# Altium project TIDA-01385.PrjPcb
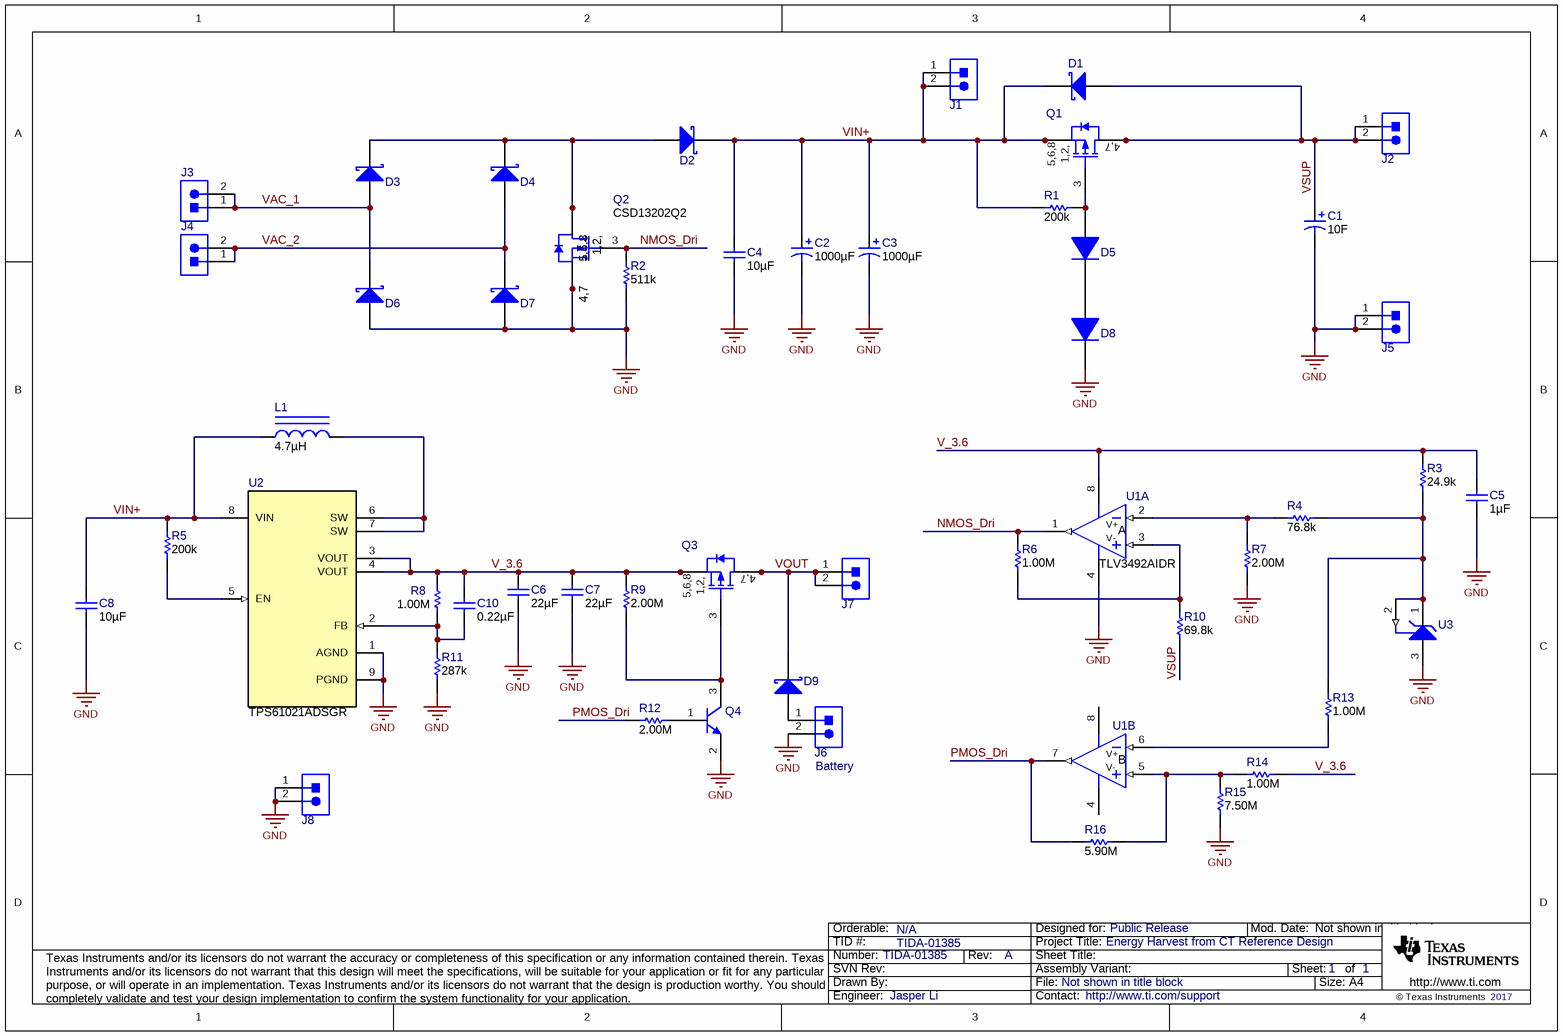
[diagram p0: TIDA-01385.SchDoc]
TID: TIDA-01385; TechSupport: http://www.ti.com/support; SCH_Rev: A; PRJ_Title: Energy Harvest from CT Reference Design; PRJ_Number: TIDA-01385; PRJ_Engineer: Jasper Li; PRJ_Customer: Public Release; PCB_Rev: A; PCB_Layout: Jasper Li; EVM_orderable: N/A; CopyrightYear: 2017
1 sheet, 50 parts. Net scope: global (net labels, ports and power ports of the same name join across sheets).
Board file: TIDA-01385_PCB.PcbDoc

## Sheet TIDA-01385.SchDoc
size A4; Date: Not shown in title block; ApprovedBy: Not shown in title block; CheckedBy: Not shown in title block; Author: Not shown in title block; CompanyName: Not shown in title block; Engineer: Not shown in title block; Organization: Not shown in title block; Address1: Not shown in title block; Address2: Not shown in title block; Address3: Not shown in title block; Address4: Not shown in title block; DocumentNumber: 1; Revision: Use project parameter SCH_Rev; SheetNumber: 1; SheetTotal: 1; PageSetup: Record=PageOptions¦CenterHorizontal=True¦CenterVertical=True¦PrintScale=0.91¦XCorrection=1.00¦YCorrection=1.00¦PrintKind=0¦BorderSize=5000000¦LeftOffset=0¦BottomOffset=0¦Orientation=2¦PaperLength=1000¦PaperWidth=1000¦Scale=100¦PaperSource=15¦PrintQuality=600¦MediaType=1¦DitherType=10¦PrintScaleMode=1¦PaperKind=Letter

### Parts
C1  ValueDisplayed: 10F  [ZL_1000x2300]  (hidden comment: 100ZL100MEFC10X23)
C2  ValueDisplayed: 1000µF  [EB_1000x2000]  (hidden comment: EEU-EB1C102)
C3  ValueDisplayed: 1000µF  [EB_1000x2000]  (hidden comment: EEU-EB1C102)
C4  ValueDisplayed: 10µF  [0603]  (hidden comment: GRM188R60J106ME47D)
C5  ValueDisplayed: 1µF  [0603]  (hidden comment: GRM185R60J105KE26D)
C6  ValueDisplayed: 22µF  [0603]  (hidden comment: GRM188R60J226MEA0D)
C7  ValueDisplayed: 22µF  [0603]  (hidden comment: GRM188R60J226MEA0D)
C8  ValueDisplayed: 10µF  [0603]  (hidden comment: GRM188R60J106ME47D)
C10  ValueDisplayed: 0.22µF  [0603]  (hidden comment: GRM188R61A224KA01D)
D1  SL22-E3/52T  [SMB]  (value not drawn)
D2  SL22-E3/52T  [SMB]  (value not drawn)
D3  SL22-E3/52T  [SMB]  (value not drawn)
D4  SL22-E3/52T  [SMB]  (value not drawn)
D5  1N4148W-7-F  [SOD-123]  (value not drawn)
D6  SL22-E3/52T  [SMB]  (value not drawn)
D7  SL22-E3/52T  [SMB]  (value not drawn)
D8  1N4148W-7-F  [SOD-123]  (value not drawn)
D9  BAT54WS-7-F  [SOD-323]  (value not drawn)
J1  TSW-102-07-G-S  [TSW-102-07-G-S]  (value not drawn)
J2  TSW-102-07-G-S  [TSW-102-07-G-S]  (value not drawn)
J3  TSW-102-07-G-S  [TSW-102-07-G-S]  (value not drawn)
J4  TSW-102-07-G-S  [TSW-102-07-G-S]  (value not drawn)
J5  TSW-102-07-G-S  [TSW-102-07-G-S]  (value not drawn)
J6  TSW-102-07-G-S  [TSW-102-07-G-S]  (value not drawn)
J7  TSW-102-07-G-S  [TSW-102-07-G-S]  (value not drawn)
J8  TSW-102-07-G-S  [TSW-102-07-G-S]  (value not drawn)
L1  ValueDisplayed: 4.7µH  [WE-PMI_1008]  (hidden comment: 74479887247)
Q1  CSD25310Q2  [DQK0006C]  (value not drawn)
Q2  CSD13202Q2  [DQK0006C]
Q3  CSD25310Q2  [DQK0006C]  (value not drawn)
Q4  MMBT3904  [SOT-23]  (value not drawn)
R1  ValueDisplayed: 200k  [0603]  (hidden comment: CRCW0603200KFKEA)
R2  ValueDisplayed: 511k  [0603]  (hidden comment: RC0603FR-07511KL)
R3  ValueDisplayed: 24.9k  [0603]  (hidden comment: CRCW060324K9FKEA)
R4  ValueDisplayed: 76.8k  [0603]  (hidden comment: CRCW060376K8FKEA)
R5  ValueDisplayed: 200k  [0603]  (hidden comment: CRCW0603200KFKEA)
R6  ValueDisplayed: 1.00M  [0603]  (hidden comment: CRCW06031M00FKEA)
R7  ValueDisplayed: 2.00M  [0603]  (hidden comment: CRCW06032M00FKEA)
R8  ValueDisplayed: 1.00M  [0603]  (hidden comment: CRCW06031M00FKEA)
R9  ValueDisplayed: 2.00M  [0603]  (hidden comment: CRCW06032M00FKEA)
R10  ValueDisplayed: 69.8k  [0603]  (hidden comment: RC0603FR-0769K8L)
R11  ValueDisplayed: 287k  [0603]  (hidden comment: CRCW0603287KFKEA)
R12  ValueDisplayed: 2.00M  [0603]  (hidden comment: CRCW06032M00FKEA)
R13  ValueDisplayed: 1.00M  [0603]  (hidden comment: CRCW06031M00FKEA)
R14  ValueDisplayed: 1.00M  [0603]  (hidden comment: CRCW06031M00FKEA)
R15  ValueDisplayed: 7.50M  [0603]  (hidden comment: CRCW06037M50FKEA)
R16  ValueDisplayed: 5.90M  [0603]  (hidden comment: CRCW06035M90FKEA)
U1  TLV3492AIDR  [D0008A_N]  (parts A,B of 2)
U2  TPS61021ADSGR  [DSG0008A]
U3  ATL431AIDBZR  [DBZ0003A_N]  (value not drawn)

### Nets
GND: C1.2(-) C2.2(-) C3.2(-) C4.2 C5.2 C6.2 C7.2 C8.2 D6.2(A) D7.2(A) D8.1(K) J5.1 J5.2 J6.2 J8.1 J8.2 Q2.4(S) Q2.7(S) Q4.2(E) R2.1 R7.1 R11.1 R15.1 U1.4(V-) U2.1(AGND) U2.9(PGND) U3.3(ANODE)
NMOS_Dri: Q2.3(G) R2.2 R6.2 U1.1(OUT)
PMOS_Dri: R12.2 R16.2 U1.7(OUT)
V_3.6: C5.1 C6.1 C7.1 C10.1 Q3.1(S) Q3.2(S) Q3.5(S) Q3.6(S) Q3.8(S) R3.2 R8.2 R9.2 R14.1 U1.8(V+) U2.3(VOUT) U2.4(VOUT)
VAC_1: D3.2(A) D6.1(K) J3.1 J3.2
VAC_2: D4.2(A) D7.1(K) J4.1 J4.2
VIN+: C2.1(+) C3.1(+) C4.1 C8.1 D1.1(K) D2.1(K) J1.1 J1.2 L1.1 Q1.1(S) Q1.2(S) Q1.5(S) Q1.6(S) Q1.8(S) R1.1 R5.2 U2.8(VIN)
VOUT: D9.1(K) J7.1 J7.2 Q3.4(D) Q3.7(D)
VSUP: C1.1(+) D1.2(A) J2.1 J2.2 Q1.4(D) Q1.7(D) R10.1
NetC10_2: C10.2 R8.1 R11.2 U2.2(FB)
NetD2_2: D2.2(A) D3.1(K) D4.1(K) Q2.1(D) Q2.2(D) Q2.5(D) Q2.6(D) Q2.8(D)
NetD5_1: D5.1(K) D8.2(A)
NetD5_2: D5.2(A) Q1.3(G) R1.2
NetD9_2: D9.2(A) J6.1
NetL1_2: L1.2 U2.6(SW) U2.7(SW)
NetQ3_3: Q3.3(G) Q4.3(C) R9.1
NetQ4_1: Q4.1(B) R12.1
NetR3_1: R3.1 R4.2 R13.1 U3.1(CATHODE) U3.2(REF)
NetR4_1: R4.1 R7.2 U1.2(IN-)
NetR5_1: R5.1 U2.5(EN)
NetR6_1: R6.1 R10.2 U1.3(IN+)
NetR13_2: R13.2 U1.6(IN-)
NetR14_2: R14.2 R15.2 R16.1 U1.5(IN+)

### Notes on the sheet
- (near J6) Battery

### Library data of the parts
C1 = 100ZL100MEFC10X23: CAP, AL, 100 µF, 100 V, +/- 20%, 0.12 ohm, TH; Manufacturer: Rubycon; Polarized: Y; CompType: Capacitor; Value: 100uF; U/M: EA; Cap_F: 0.0001; Tolerance_%: 20; VDC_V: 100; Value2: 100V; ESR_ohm: 0.12; IRMS_A: 0.88; TaMin_C: -40; TaMax_C: 105; Cap_Case: 10x23mm; SizeAreaWB_mm2: 144; SizeX_mm: 10; SizeZ_mm: 25; AEC Category: Q200; AEC Qualified: N
C2 C3 = EEU-EB1C102: CAP, AL, 1000 µF, 16 V, +/- 20%, TH; Manufacturer: Panasonic; Polarized: Y; CompType: Capacitor; Value: 1000uF; U/M: EA; Cap_F: 0.001; Tolerance_%: 20; Value1: Unknown; VDC_V: 16; Value2: 16V; IRMS_A: 0.43; TaMin_C: -40; TaMax_C: 105; Cap_Case: 10x20mm; SizeAreaWB_mm2: 144; SizeArea_mm2: 100; SizeX_mm: 10; SizeZ_mm: 22; AEC Category: Q200; AEC Qualified: N
C4 C8 = GRM188R60J106ME47D: CAP, CERM, 10 µF, 6.3 V, +/- 20%, X5R, 0603; Manufacturer: MuRata; Polarized: N; CompType: Capacitor; Value: 10uF; U/M: EA; Cap_F: 0.00001; Tolerance_%: 20; ESR_ohm: 0.009; Value1: 0.009 ohm; VDC_V: 6.3; Value2: 6.3V; IRMS_A: 2.74; TaMin_C: -55; TaMax_C: 125; SizeArea_mm2: 1.28; SizeAreaWB_mm2: 4.68; SizeX_mm: 1.6; SizeY_mm: 0.8; SizeZ_mm: 1; AEC Category: Q200
C5 = GRM185R60J105KE26D: CAP, CERM, 1 µF, 6.3 V, +/- 10%, X5R, 0603; Manufacturer: MuRata; Polarized: N; CompType: Capacitor; Value: 1uF; U/M: EA; Cap_F: 0.000001; Tolerance_%: 10; Value1: Unknown; VDC_V: 6.3; Value2: 6.3V; TaMin_C: -55; TaMax_C: 85; SizeArea_mm2: 1.28; SizeAreaWB_mm2: 4.68; SizeX_mm: 1.6; SizeY_mm: 0.8; SizeZ_mm: 1; AEC Category: Q200
C6 C7 = GRM188R60J226MEA0D: CAP, CERM, 22 µF, 6.3 V, +/- 20%, X5R, 0603; Manufacturer: MuRata; Polarized: N; CompType: Capacitor; Value: 22uF; U/M: EA; Cap_F: 0.000022; Tolerance_%: 20; Value1: Unknown; VDC_V: 6.3; Value2: 6.3V; TaMin_C: -55; TaMax_C: 85; SizeArea_mm2: 1.28; SizeAreaWB_mm2: 4.68; SizeX_mm: 1.6; SizeY_mm: 0.8; SizeZ_mm: 1; AEC Category: Q200
C10 = GRM188R61A224KA01D: CAP, CERM, 0.22 µF, 10 V, +/- 10%, X5R, 0603; Manufacturer: MuRata; Polarized: N; CompType: Capacitor; Value: 0.22uF; U/M: EA; Cap_F: 0.00000022; Tolerance_%: 10; Value1: Unknown; Value2: 10V; TaMin_C: -55; TaMax_C: 85; SizeArea_mm2: 1.28; SizeAreaWB_mm2: 4.68; SizeX_mm: 1.6; SizeY_mm: 0.8; SizeZ_mm: 1; AEC Category: Q200
D1-D4 D6 D7 = SL22-E3/52T: Diode, Schottky, 20 V, 2 A, SMB; Manufacturer: Vishay-Semiconductor; U/M: EA; Vf_V: 0.44; Value: 20V; Value1: 2A; Value2: 0.44V; Io_A: 2; Vr_V: 20; TJmax_C: 125; RJC_CperW: 17; SizeAreaWB_mm2: 44.156; SizeArea_mm2: 21.336; SizeX_mm: 5.6; SizeY_mm: 3.81; SizeZ_mm: 2.6; AEC Category: Q101
D5 D8 = 1N4148W-7-F: Diode, Ultrafast, 100 V, 0.15 A, SOD-123; Manufacturer: Diodes Inc.; U/M: EA; Vf_V: 1.25; Value: 100V; Value1: 0.15A; Value2: 1.25V; Io_A: 0.15; Vr_V: 100; TJmax_C: 150; SizeAreaWB_mm2: 13.095; SizeArea_mm2: 6.545; SizeX_mm: 3.85; SizeY_mm: 1.7; SizeZ_mm: 1.35; AEC Category: Q101
D9 = BAT54WS-7-F: Diode, Schottky, 30 V, 0.2 A, SOD-323; Manufacturer: Diodes Inc.; U/M: EA; Vf_V: 0.7; Value: 30V; Value1: 0.2A; Value2: 0.7V; Io_A: 0.2; Vr_V: 30; TJmax_C: 125; SizeAreaWB_mm2: 8.695; SizeArea_mm2: 3.645; SizeX_mm: 2.7; SizeY_mm: 1.35; SizeZ_mm: 1; AEC Category: Q101
J1-J8 = TSW-102-07-G-S: Header, 100mil, 2x1, Gold, TH; Manufacturer: Samtec; SymbolCreator: a0412235; Pitch_mm: 2.54; Gender: Male; Shrouded: N; Row_Count: 1; Current_A: 6.3; Voltage_V: 550; Cert_CSA: Y
L1 = 74479887247: Inductor, Shielded Drum Core, Metal Composite, 4.7 µH, 0.75 A, 0.53 ohm, SMD; Manufacturer: Wurth Elektronik; Value: 4.7uH; Ind_H: 4.7E-6; Imax_A: 0.75; Irms: 0.75A @ 40C rise; Isat: 0.85A @ 30% inductance drop; DCR_ohm: 0.53; Value2: 0.75A; SizeAreaWB_mm2: 10.5; SizeArea_mm2: 5; SizeX_mm: 2.5; SizeY_mm: 2; SizeZ_mm: 1; AEC Category: Q200
Q1 Q3 = CSD25310Q2: MOSFET, P-CH, -20 V, -20 A, DQK0006C (WSON-6); Manufacturer: Texas Instruments; Alternate Manufacturer: None; SymbolCreator: a0411947; U/M: EA; ChType: P; Value: -20V; Value1: 0.0239 ohm; Rdson45_ohm: 0.0239; Value2: 3.6 nC; QgTyp_nC: 3.6; Vgs_V: -8; SizeAreaWB_mm2: 9; SizeArea_mm2: 4; SizeX_mm: 2; SizeZ_mm: 0.8; AEC Category: Q101
Q2 = CSD13202Q2: MOSFET, N-CH, 12 V, 22 A, DQK0006C (WSON-6); Manufacturer: Texas Instruments; Alternate Manufacturer: None; U/M: EA; ChType: N; Value: 12V; VdsMax_V: 12; Value1: 0.0093 ohm; Rdson45_ohm: 0.0093; Value2: 5.1 nC; QgTyp_nC: 5.1; Vgs_V: 8; IdsMax_A: 22; SizeAreaWB_mm2: 9; SizeArea_mm2: 4; SizeX_mm: 2; SizeZ_mm: 0.8; AEC Category: Q101
Q4 = MMBT3904, Fairchild Semiconductor: Transistor, NPN, 40 V, 0.2 A, SOT-23; CompType: BJT; PNP: 0; NPN: 1; Vceo_V: 40; Vcesat1_V: 0.2; Value: 40 V; Value1: 0.2 A; HfeMax: 300; TaMin_C: -55; TaMax_C: 150; SizeAreaWB_mm2: 14; SizeArea_mm2: 7.5; SizeX_mm: 2.5; SizeY_mm: 3; SizeZ_mm: 1.1; U/M: EA; AEC Category: Q101
R1 R5 = CRCW0603200KFKEA: RES, 200 k, 1%, 0.1 W, 0603; Manufacturer: Vishay-Dale; CompType: Resistor; Value: 200k; Res_ohm: 200000; Tolerance_%: 1; Power_W: 0.1; Value2: 0.1W; VDC_V: 75; TempCo: 100 ppm/C; SizeArea_mm2: 1.28; SizeX_mm: 1.6; SizeY_mm: 0.8; EIA_Code: E96; U/M: EA; AEC Category: Q200
R2 = RC0603FR-07511KL: RES, 511 k, 1%, 0.1 W, 0603; Manufacturer: Yageo America; CompType: Resistor; Value: 511k; Res_ohm: 511000; Tolerance_%: 1; Power_W: 0.1; Value2: 0.1W; VDC_V: 150; TempCo: 200 ppm/C; SizeArea_mm2: 1.28; SizeX_mm: 1.6; SizeY_mm: 0.8; EIA_Code: E96; U/M: EA; AEC Category: Q200
R3 = CRCW060324K9FKEA: RES, 24.9 k, 1%, 0.1 W, 0603; Manufacturer: Vishay-Dale; CompType: Resistor; Value: 24.9k; Res_ohm: 24900; Value_Code: 24k9; Tolerance_%: 1; Power_W: 0.1; Value2: 0.1W; VDC_V: 75; TempCo: 100 ppm/C; SizeArea_mm2: 1.28; SizeX_mm: 1.6; SizeY_mm: 0.8; EIA_Code: E96; U/M: EA; AEC Category: Q200
R4 = CRCW060376K8FKEA: RES, 76.8 k, 1%, 0.1 W, 0603; Manufacturer: Vishay-Dale; CompType: Resistor; Value: 76.8k; Res_ohm: 76800; Value_Code: 76k8; Tolerance_%: 1; Power_W: 0.1; Value2: 0.1W; VDC_V: 75; TempCo: 100 ppm/C; SizeArea_mm2: 1.28; SizeX_mm: 1.6; SizeY_mm: 0.8; EIA_Code: E96; U/M: EA; AEC Category: Q200
R6 R8 R13 R14 = CRCW06031M00FKEA: RES, 1.00 M, 1%, 0.1 W, 0603; Manufacturer: Vishay-Dale; CompType: Resistor; Value: 1.00Meg; Res_ohm: 1000000; Value_Code: 1M00; Tolerance_%: 1; Power_W: 0.1; Value2: 0.1W; VDC_V: 75; TempCo: 100 ppm/C; SizeArea_mm2: 1.28; SizeX_mm: 1.6; SizeY_mm: 0.8; EIA_Code: E96; U/M: EA; AEC Category: Q200
R7 R9 R12 = CRCW06032M00FKEA: RES, 2.00 M, 1%, 0.1 W, 0603; Manufacturer: Vishay-Dale; CompType: Resistor; Value: 2.00Meg; Res_ohm: 2000000; Value_Code: 2M00; Tolerance_%: 1; Power_W: 0.1; Value2: 0.1W; VDC_V: 75; TempCo: 100 ppm/C; SizeArea_mm2: 1.28; SizeX_mm: 1.6; SizeY_mm: 0.8; EIA_Code: E96; U/M: EA; AEC Category: Q200
R10 = RC0603FR-0769K8L: RES, 69.8 k, 1%, 0.1 W, 0603; Manufacturer: Yageo America; CompType: Resistor; Value: 69.8k; Res_ohm: 69800; Value_Code: 69k8; Tolerance_%: 1; Power_W: 0.1; Value2: 0.1W; VDC_V: 150; TempCo: 200 ppm/C; SizeArea_mm2: 1.28; SizeX_mm: 1.6; SizeY_mm: 0.8; EIA_Code: E96; U/M: EA; AEC Category: Q200
R11 = CRCW0603287KFKEA: RES, 287 k, 1%, 0.1 W, 0603; Manufacturer: Vishay-Dale; CompType: Resistor; Value: 287k; Res_ohm: 287000; Tolerance_%: 1; Power_W: 0.1; Value2: 0.1W; VDC_V: 75; TempCo: 100 ppm/C; SizeArea_mm2: 1.28; SizeX_mm: 1.6; SizeY_mm: 0.8; EIA_Code: E96; U/M: EA; AEC Category: Q200
R15 = CRCW06037M50FKEA: RES, 7.50 M, 1%, 0.1 W, 0603; Manufacturer: Vishay-Dale; CompType: Resistor; Value: 7.50Meg; Res_ohm: 7500000; Value_Code: 7M50; Tolerance_%: 1; Power_W: 0.1; Value2: 0.1W; VDC_V: 75; TempCo: 100 ppm/C; SizeArea_mm2: 1.28; SizeX_mm: 1.6; SizeY_mm: 0.8; EIA_Code: E96; U/M: EA; AEC Category: Q200
R16 = CRCW06035M90FKEA: RES, 5.90 M, 1%, 0.1 W, 0603; Manufacturer: Vishay-Dale; CompType: Resistor; Value: 5.90Meg; Res_ohm: 5900000; Value_Code: 5M90; Tolerance_%: 1; Power_W: 0.1; Value2: 0.1W; VDC_V: 75; TempCo: 100 ppm/C; SizeArea_mm2: 1.28; SizeX_mm: 1.6; SizeY_mm: 0.8; EIA_Code: E96; U/M: EA; AEC Category: Q200
U1 = TLV3492AIDR: 1.8V, Nanopower, PUSH-PULL OUTPUT COMPARATOR, D0008A (SOIC-8); Manufacturer: Texas Instruments; CompType: IC; SizeArea_mm2: 30.38; SizeAreaWB_mm2: 56.58; SizeX_mm: 4.9; SizeY_mm: 6.2; SizeZ_mm: 1.75; U/M: EA
U2 = TPS61021ADSGR: 3-A BOOST CONVERTER WITH 0.5V ULTRA-LOW INPUT VOLTAGE, DSG0008A (WSON-8); Alternate PartNumber: TPS61021ADSGT; Manufacturer: Texas Instruments; SymbolCreator: Altium; SizeArea_mm2: 4; SizeAreaWB_mm2: 9; SizeX_mm: 2; SizeZ_mm: 0.8; CompType: IC; U/M: EA
U3 = ATL431AIDBZR: 2.5V Low Iq Adjustable Precision Shunt Regulator, DBZ0003A (SOP-3); Manufacturer: Texas Instruments; SymbolCreator: a0412235; SizeArea_mm2: 7.5; SizeAreaWB_mm2: 14; SizeX_mm: 2.5; SizeY_mm: 3; SizeZ_mm: 1.12; CompType: IC; U/M: EA

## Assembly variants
001: not fitted C3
